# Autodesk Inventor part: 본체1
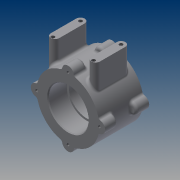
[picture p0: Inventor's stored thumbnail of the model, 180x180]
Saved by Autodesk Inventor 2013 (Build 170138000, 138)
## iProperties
Created: 2015-03
Part Number: 본체1
Material: 일반
Document SubType Name: Modeling
Designer: cad8
Density: 1 g/cm^3
Author: cad8
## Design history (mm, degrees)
sketch "스케치1"
  geometry: C1 r 37 at (0, 0); 1 further point
  constraints: 1 centre point, 1 coincident
  dimensions: "d0" = 74 diameter of C1
extrude "돌출1" new body sketch "스케치1" distance "d2" = 52; taper "d3" = 0 deg
sketch "스케치2" dims "d4" = 74
  geometry: L1 (0, 2.614)-(0, 37); C1 r 37 at (0, 0) reference; C2 r 7 at (0, 37); 1 further point
  constraints: 2 coincident, 2 end point, 1 centre point, 1 vertical, 1 vertical alignment, 2 other
  dimensions: "d6" = 14 diameter of C2
extrude "돌출2" join sketch "스케치2" distance "d7" = 15; taper "d8" = 0 deg
sketch "스케치3"
  geometry: A1 r 7 centre (0, 37) between (6.969, 36.338) and (-6.969, 36.338) reference; 1 further point
  constraints: 1 coincident
hole "구멍1" sketch "스케치3" at (0, 37) diameter "d9" = 3.242; stored, may be unused: countersink angle "d13" = 90 deg, drill point angle "d15" = 118 deg; dims "d10" = 8, "d11" = 4, "d12" = 2, "d14" = 11
node "작업 평면1"
node "작업 평면2"
sketch "스케치4"
  geometry: L1 (-37, 15)-(-37, 37) reference; L2 (37, 15)-(37, 37) reference; L3 (36.338, 52)-(36.338, 37) reference; L4 (36.338, 37)-(36.338, 37) reference; L5 (36.338, 37)-(36.338, 52) reference; L6 (6.969, 52)-(36.338, 52) reference; L7 (6.969, 52)-(6.969, 37) reference; L8 (6.969, 37)-(-6.969, 37) reference; L9 (-6.969, 37)-(-6.969, 52) reference; L10 (-36.338, 52)-(-6.969, 52) reference; L11 (-36.338, 52)-(-36.338, 37) reference; L12 (-36.338, 37)-(-36.338, 37) reference; L13 (-36.338, 37)-(-36.338, 52) reference; L14 (-6.969, 52)-(-36.338, 52) reference; L15 (-6.969, 52)-(-6.969, 37) reference; L16 (-6.969, 37)-(6.969, 37) reference; L17 (6.969, 37)-(6.969, 52) reference; L18 (36.338, 52)-(6.969, 52) reference; L19 (36.338, 0)-(36.338, 15) reference; L20 (36.338, 15)-(36.338, 15) reference; L21 (36.338, 15)-(36.338, 0) reference; L22 (6.969, 0)-(36.338, 0) reference; L23 (6.969, 0)-(6.969, 15) reference; L24 (6.969, 15)-(-6.969, 15) reference; L25 (-6.969, 15)-(-6.969, 0) reference; L26 (-36.338, 0)-(-6.969, 0) reference; L27 (-36.338, 0)-(-36.338, 15) reference; L28 (-36.338, 15)-(-36.338, 15) reference; L29 (-36.338, 15)-(-36.338, 0) reference; L30 (-6.969, 0)-(-36.338, 0) reference; L31 (-6.969, 0)-(-6.969, 15) reference; L32 (-6.969, 15)-(6.969, 15) reference; L33 (6.969, 15)-(6.969, 0) reference; L34 (36.338, 0)-(6.969, 0) reference; L35 (-6.969, 52)-(-6.969, 37) reference; L36 (-6.969, 52)-(6.969, 52) reference; L37 (6.969, 37)-(6.969, 52) reference; L38 (-6.969, 37)-(6.969, 37) reference; L39 (-6.969, 15)-(-6.969, 0) reference; L40 (-6.969, 15)-(6.969, 15) reference; L41 (6.969, 0)-(6.969, 15) reference; L42 (-6.969, 0)-(6.969, 0) reference; L43 (-37, 26)-(3.417, 26); L44 (0, 0)-(0, 30.982); L45 (-31.294, 46)-(-21.294, 46); L46 (-21.294, 46)-(-21.294, 6); L47 (-21.294, 6)-(-31.294, 6); L48 (-31.294, 6)-(-31.294, 46); L49 (16.706, 46)-(26.706, 46); L50 (26.706, 46)-(26.706, 6); L51 (26.706, 6)-(16.706, 6); L52 (16.706, 6)-(16.706, 46); L53 (-26.294, 6)-(-26.294, 15); L54 (21.706, 6)-(21.706, 13.564); 2 further points
  constraints: 24 end point, 7 parallel, 5 midpoint, 3 perpendicular, 2 horizontal, 2 horizontal alignment, 1 other
  dimensions: "d20" = 10 distance of L45.start L45.end; "d22" = 10 distance of L49.start L49.end; "d23" = 48 distance between parallel lines of L54 L53; "d24" = 40 distance between parallel lines of L51 L49
extrude "돌출3" join sketch "스케치4" distance "d25" = 56; taper "d26" = 0 deg
node "작업 평면3"
sketch "스케치5"
  geometry: L1 (-21.294, 46)-(-31.294, 46) reference; L2 (-31.294, 46)-(-31.294, 6) reference; L3 (-31.294, 6)-(-21.294, 6) reference; L4 (-21.294, 6)-(-21.294, 46) reference; L5 (26.706, 46)-(16.706, 46) reference; L6 (16.706, 46)-(16.706, 6) reference; L7 (16.706, 6)-(26.706, 6) reference; L8 (26.706, 6)-(26.706, 46) reference; L9 (6.969, 52)-(6.969, 37) reference; L10 (6.969, 52)-(-6.969, 52) reference; L11 (-6.969, 37)-(-6.969, 52) reference; L12 (6.969, 37)-(-6.969, 37) reference; L13 (-21.294, 46)-(-21.294, 6) reference; L14 (-21.294, 6)-(-31.294, 6) reference; L15 (-31.294, 6)-(-31.294, 46) reference; L16 (-31.294, 46)-(-21.294, 46) reference; L17 (26.706, 46)-(26.706, 6) reference; L18 (26.706, 6)-(16.706, 6) reference; L19 (16.706, 6)-(16.706, 46) reference; L20 (16.706, 46)-(26.706, 46) reference; L21 (36.338, 52)-(36.338, 37) reference; L22 (36.338, 37)-(36.338, 37) reference; L23 (36.338, 37)-(36.338, 52) reference; L24 (6.969, 52)-(36.338, 52) reference; L25 (6.969, 52)-(6.969, 37) reference; L26 (6.969, 37)-(-6.969, 37) reference; L27 (-6.969, 37)-(-6.969, 52) reference; L28 (-36.338, 52)-(-6.969, 52) reference; L29 (-36.338, 52)-(-36.338, 37) reference; L30 (-36.338, 37)-(-36.338, 37) reference; L31 (-36.338, 37)-(-36.338, 52) reference; L32 (-6.969, 52)-(-36.338, 52) reference; L33 (-6.969, 52)-(-6.969, 37) reference; L34 (-6.969, 37)-(6.969, 37) reference; L35 (6.969, 37)-(6.969, 52) reference; L36 (36.338, 52)-(6.969, 52) reference; L37 (36.338, 0)-(36.338, 15) reference; L38 (36.338, 15)-(36.338, 15) reference; L39 (36.338, 15)-(36.338, 0) reference; L40 (6.969, 0)-(36.338, 0) reference; L41 (6.969, 0)-(6.969, 15) reference; L42 (6.969, 15)-(-6.969, 15) reference; L43 (-6.969, 15)-(-6.969, 0) reference; L44 (-36.338, 0)-(-6.969, 0) reference; L45 (-36.338, 0)-(-36.338, 15) reference; L46 (-36.338, 15)-(-36.338, 15) reference; L47 (-36.338, 15)-(-36.338, 0) reference; L48 (-6.969, 0)-(-36.338, 0) reference; L49 (-6.969, 0)-(-6.969, 15) reference; L50 (-6.969, 15)-(6.969, 15) reference; L51 (6.969, 15)-(6.969, 0) reference; L52 (36.338, 0)-(6.969, 0) reference; L53 (-37, 15)-(-37, 37) reference; L54 (-31.294, 26)-(-15.141, 26); L55 (0, 37)-(0, 36.039); L56 (0, 52)-(0, 42.132); L57 (-26.294, 46)-(-26.294, 43.607); 6 further points
  constraints: 8 end point, 5 midpoint, 3 vertical alignment, 2 perpendicular, 1 collinear, 1 horizontal alignment, 1 parallel
  dimensions: "d34" = 48 distance of point (21.706, 41) point (-26.294, 41); "d36" = 5 distance from line of L5 point (21.706, 41); "d37" = 5 distance from line of L1 point (-26.294, 41)
hole "구멍2" sketch "스케치5" at (-26.294, 41), (21.706, 41), (-26.294, 8.41), (21.706, 8.41) diameter "d40" = 4.134; stored, may be unused: countersink angle "d44" = 90 deg, drill point angle "d46" = 118 deg; dims "d41" = 6, "d42" = 4, "d43" = 2, "d45" = 8
sketch "스케치6"
  geometry: C1 r 23.5 at (0, 0); A1 r 37 centre (0, 0) between (6.969, -36.338) and (36.338, -6.969) reference
  constraints: 1 centre point, 1 coincident
  dimensions: "d47" = 47 diameter of C1
extrude "돌출4" cut sketch "스케치6" distance "d49" = 22; taper "d50" = 0 deg
sketch "스케치7"
  geometry: C1 r 23.5 at (0, 0); A1 r 37 centre (0, 0) between (6.969, -36.338) and (36.338, -6.969) reference
  constraints: 1 centre point, 1 coincident
  dimensions: "d51" = 47 diameter of C1
extrude "돌출5" cut sketch "스케치7" distance "d53" = 22; taper "d54" = 0 deg
sketch "스케치8"
  geometry: C1 r 23.5 at (0, 0) reference; C2 r 21 at (0, 0)
  constraints: 1 centre point, 1 coincident
  dimensions: "d55" = 42 diameter of C2
extrude "돌출6" cut sketch "스케치8" distance "d57" = 22; taper "d58" = 0 deg
fillet "모깎기1" dims "d59" = 5
fillet "모깎기2" dims "d60" = 0.3
fillet "모깎기3" dims "d61" = 3
fillet "모깎기4" dims "d62" = 3
chamfer "모따기1" distance "d63" = 1; stored, may be unused: second distance "d64" = 2, angle "d65" = 45 deg
chamfer "모따기2" distance "d66" = 1; stored, may be unused: second distance "d67" = 2, angle "d68" = 45 deg
node "작업 평면5"
  node "작업 평면4"
sketch "스케치9"
  geometry: L1 (0, -18.921)-(0, 18.921) reference; L2 (-30.3, 23.5)-(-30.3, -23.5) reference; L3 (-62.4, 0)-(10.4, 0) reference; 2 further points
  constraints: 1 other
  dimensions: "d70" = 26 distance of point (-26, 0) point (0, 0); "d71" = 0 distance from line of L3 point (-26, 0)
feature "엠보싱1" sketch "스케치9" dims "d2" = 52, "d3" = 0, "d72" = 0.5, "d73" = 0
node "솔리드1"
pattern_circular "원형 패턴1" dims angle "d17" = 360 deg
mirror "대칭1"
node "투영된 루프1"
node "투영된 루프2"
node "투영된 루프3"
node "투영된 루프4"
node "투영된 루프5"
node "투영된 루프6"
node "투영된 루프7"
node "작업축1"
other parameters: "d19" = 0, "d27" = 56, "d69" = 135 deg
